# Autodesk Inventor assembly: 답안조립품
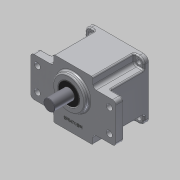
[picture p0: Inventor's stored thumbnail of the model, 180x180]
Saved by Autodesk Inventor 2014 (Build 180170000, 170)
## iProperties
Created: 2014-12
Part Number: 답안조립품
Document SubType Name: Assembly
Designer: user
Author: user
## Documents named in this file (12)
- C:\Users\user\Desktop\Inventor2급-김민한\답안조립품.iam
- C:\Users\user\Desktop\Inventor2급-김민한\본체.ipt
- C:\Users\user\Desktop\Inventor2급-김민한\오일실 17x32x8.ipt
- C:\Users\user\Desktop\Inventor2급-김민한\베어링 6003.ipt
- 베어링 6003.ipt
- C:\Users\user\Desktop\Inventor2급-김민한\베어링 608.ipt
- 베어링 608.ipt
- C:\Users\user\Desktop\Inventor2급-김민한\서브축.ipt
- C:\Users\user\Desktop\Inventor2급-김민한\메인축.ipt
- C:\Users\user\Desktop\Inventor2급-김민한\커버.ipt
- C:\Users\user\Desktop\Inventor2급-김민한\오일실 8x22x7.ipt
- C:\Users\user\Desktop\Inventor2급-김민한\M4x0.5x16.ipt
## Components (4 placed, 1 different names)
1. M4x0.5x12:1
2. M4x0.5x12:2
3. M4x0.5x12:3
4. M4x0.5x12:4
